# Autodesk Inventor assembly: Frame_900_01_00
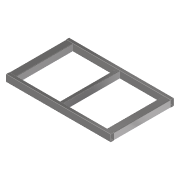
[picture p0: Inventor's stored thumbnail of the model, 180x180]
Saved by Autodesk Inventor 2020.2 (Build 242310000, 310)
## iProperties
_FrameDoc: Frame Assembly
_Version: 15.0.0
Manager: www.cadconsulting.pl
Company: Fabian Stasiak CAD Consulting
Created: 2015-10
Part Number: Frame_900_01_00
Document SubType Name: Assembly
Designer: F.Stasiak
Catalog Web Link: www.expertbooks.pl
Author: F.Stasiak
Subject: Zbiór ćwiczeń. Autodesk Inventor 2020. Kurs Professional
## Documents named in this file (12)
- C:\2020_Kurs_Professional\R3 Dynamika\900-01\Frame\Frame_900_01_00.iam
- C:\2020_Kurs_Professional\R3 Dynamika\900-01\Frame\Skeleton_900-01-00.ipt
- C:\2020_Kurs_Professional\R3 Dynamika\900-01\Frame\DIN 120x60x4 900-01-1.ipt
- DIN 120x60x4 900-01-1.ipt
- C:\2020_Kurs_Professional\R3 Dynamika\900-01\Frame\DIN 120x60x4 900-01-02.ipt
- DIN 120x60x4 900-01-02.ipt
- C:\2020_Kurs_Professional\R3 Dynamika\900-01\Frame\DIN 120x60x4 900-01-03.ipt
- DIN 120x60x4 900-01-03.ipt
- C:\2020_Kurs_Professional\R3 Dynamika\900-01\Frame\DIN 120x60x4 900-01-04.ipt
- DIN 120x60x4 900-01-04.ipt
- C:\2020_Kurs_Professional\R3 Dynamika\900-01\Frame\DIN 120x60x4 900-01-05.ipt
- DIN 120x60x4 900-01-05.ipt
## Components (6 placed, 6 different names)
1. Model odniesienia ramy
2. DIN 120x60x4 900-01-1:1
3. DIN 120x60x4 900-01-02:1
4. DIN 120x60x4 900-01-03:1
5. DIN 120x60x4 900-01-04:1
6. DIN 120x60x4 900-01-05:1
